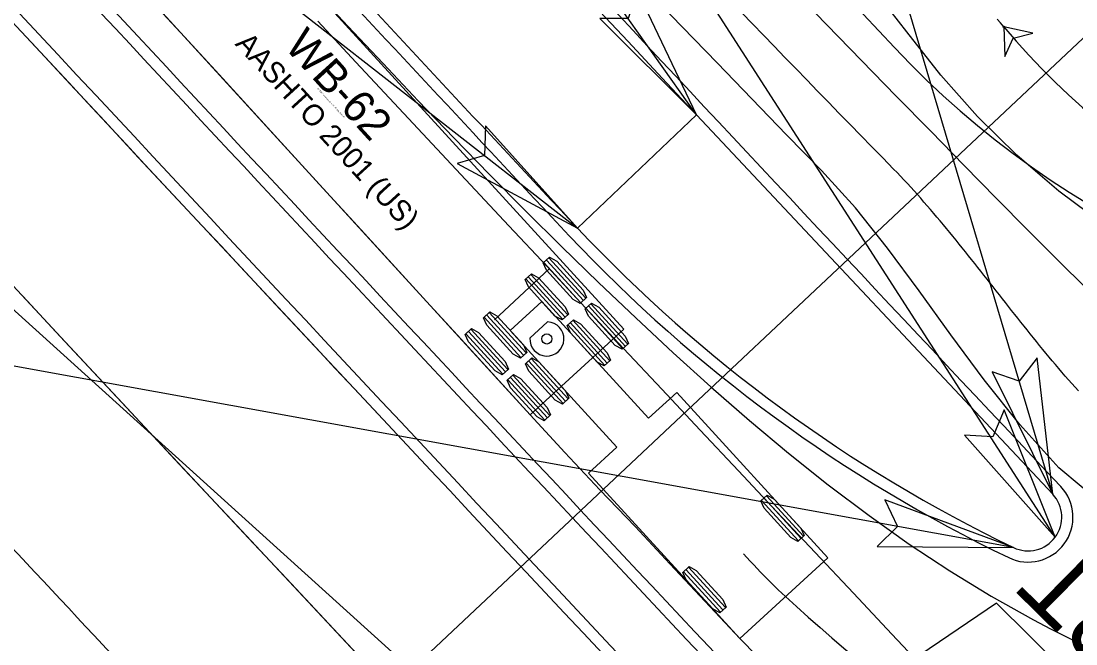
# Model space of a CAD drawing. Extents: x 1262642 to 1268358, y 767825 to 773481.
# Drawn here: x 1266689.1 to 1266759.8, y 772205.7 to 772247.4 of the extents above; entities that cross this region are included whole.
import ezdxf

# ---------------------------------------------------------------- set-up
doc = ezdxf.new("R2010")
doc.units = 0
for name, color, linetype in [('Prop Conc 1ft 6in Curb and Gutter', 7, 'Continuous'), ('Prop Conc 5in Monolithic Keyed In Island', 7, 'Continuous'), ('Prop Dimension Text', 7, 'Continuous'), ('Prop EOT', 7, 'Continuous'), ('Prop Horizontal Alignment', 7, 'Continuous'), ('Prop Horizontal Alignment Station Label', 7, 'Continuous'), ('Prop Horizontal Alignment Tick Small', 7, 'Continuous'), ('Prop Lane Lines', 7, 'Continuous'), ('Prop Paved Shoulder', 7, 'Continuous'), ('Prop Shade Light', 7, 'Continuous'), ('Prop Shade Medium', 7, 'Continuous'), ('Prop Terminator CELL', 7, 'Continuous'), ('Scratch_Level_3', 7, 'Continuous')]:
    doc.layers.add(name, color=color, linetype=linetype)

msp = doc.modelspace()

# ---------------------------------------------------------------- linework, layer by layer
at = {"layer": 'Prop Conc 1ft 6in Curb and Gutter'}
msp.add_line((1266726.388, 772233.528), (1266734.359, 772241.11), dxfattribs=at)
for radius, start, end in [(11385.75, 220.9464115, 223.1036607), (11396.75, 222.8296601, 223.1041091)]:
    msp.add_arc((1275047.307, 780021.225), radius, start, end, dxfattribs=at)
at = {"layer": 'Prop Conc 5in Monolithic Keyed In Island'}
msp.add_line((1266734.359, 772241.11), (1266758.201, 772215.712), dxfattribs=at)
for centre, radius, start, end in [((1275047.307, 780021.225), 11410.25, 222.8296601, 223.2792706), ((1275047.307, 780021.225), 11414.25, 222.8297896, 223.4298287), ((1266798.645, 772301.569), 99.25, 223.2788, 244.28592), ((1266756.558, 772214.175), 2.25, 244.28592, 43.10421)]:
    msp.add_arc(centre, radius, start, end, dxfattribs=at)
at = {"layer": 'Prop Dimension Text'}
for p, q in [((1266734.359, 772241.11), (1266654.367, 772353.573)), ((1266758.201, 772215.712), (1266729.837, 772311.282)), ((1266637.674, 772302.797), (1266726.388, 772233.528)), ((1266758.372, 772212.843), (1266700.467, 772302.683)), ((1266755.582, 772212.148), (1266643.887, 772232.407)), ((1266754.434, 772208.43), (1266782.15, 772181.121))]:
    msp.add_line(p, q, dxfattribs=at)
msp.add_lwpolyline([(1266754.434, 772208.43), (1266740.368, 772198.877)], dxfattribs=at)
at = {"layer": 'Prop EOT'}
for centre, radius, start, end in [((1275047.307, 780021.225), 11385, 222.8296601, 223.2789723), ((1275047.307, 780021.225), 11397.5, 222.8287756, 223.1041206), ((1275047.307, 780021.225), 11409.5, 222.8296601, 223.2792706), ((1275047.307, 780021.225), 11415, 222.8297896, 223.4298287), ((1266798.645, 772301.569), 100, 223.2788, 244.28592), ((1266840.27, 772443.458), 318.091, 223.23333, 243.65317), ((1275047.307, 780021.225), 11439, 222.9935866, 223.2588472), ((1266756.558, 772214.175), 3, 244.28592, 43.10421)]:
    msp.add_arc(centre, radius, start, end, dxfattribs=at)
at = {"layer": 'Prop Horizontal Alignment'}
msp.add_arc((1275047.307, 780021.225), 11400, 222.9935866, 225.4043192, dxfattribs=at)
at = {"layer": 'Prop Horizontal Alignment Station Label'}
for p, q in [((1266683.114, 772173.743), (1266860.999, 772340.982)), ((1266769.823, 772154.715), (1266566.881, 772338.064))]:
    msp.add_line(p, q, dxfattribs=at)
at = {"layer": 'Prop Horizontal Alignment Tick Small'}
msp.add_line((1266724.486, 772230.805), (1266720.835, 772227.388), dxfattribs=at)
at = {"layer": 'Prop Lane Lines'}
for centre, radius, start, end in [((1275047.307, 780021.225), 11373, 216.3649439, 223.1327476), ((1275047.307, 780021.225), 11427, 216.3674993, 223.5476842), ((1275047.307, 780021.225), 11415, 220.9464115, 223.1041206), ((1266791.4, 772286.629), 60, 223.13275, 315.73419), ((1275047.307, 780021.225), 11427, 222.9935866, 225.3637298)]:
    msp.add_arc(centre, radius, start, end, dxfattribs=at)
at = {"layer": 'Prop Paved Shoulder'}
for centre, radius, start, end in [((1275047.307, 780021.225), 11449, 220.5050908, 223.2024475), ((1266840.27, 772443.458), 314.091, 223.23333, 241.33253)]:
    msp.add_arc(centre, radius, start, end, dxfattribs=at)
at = {"layer": 'Prop Shade Light'}
for centre, radius, start, end in [((1275047.307, 780021.225), 11449, 220.5050908, 223.2024475), ((1266840.27, 772443.458), 314.091, 223.23333, 241.33253), ((1266840.27, 772443.458), 318.091, 223.23333, 243.65317), ((1275047.307, 780021.225), 11439, 222.9935866, 223.2588472)]:
    msp.add_arc(centre, radius, start, end, dxfattribs=at)
at = {"layer": 'Prop Shade Medium'}
for p, q in [((1266726.388, 772233.528), (1266734.359, 772241.11)), ((1266734.359, 772241.11), (1266758.201, 772215.712))]:
    msp.add_line(p, q, dxfattribs=at)
for centre, radius, start, end in [((1275047.307, 780021.225), 11410.25, 222.8296601, 223.2792706), ((1275047.307, 780021.225), 11414.25, 222.8297896, 223.4298287), ((1266798.645, 772301.569), 99.25, 223.2788, 244.28592), ((1266756.558, 772214.175), 2.25, 244.28592, 43.10421)]:
    msp.add_arc(centre, radius, start, end, dxfattribs=at)
at = {"layer": 'Prop Terminator CELL'}
for points in [[(1266727.879, 772247.545), (1266734.359, 772241.11), (1266730.417, 772249.412), (1266729.78, 772247.547)], [(1266718.341, 772237.845), (1266726.388, 772233.528), (1266720.24, 772240.359), (1266720.162, 772238.39)], [(1266754.152, 772223.898), (1266758.201, 772215.712), (1266757.158, 772224.843), (1266755.952, 772223.285)], [(1266752.301, 772219.665), (1266758.372, 772212.843), (1266754.949, 772221.372), (1266754.198, 772219.55)], [(1266746.45, 772212.229), (1266755.582, 772212.148), (1266746.963, 772215.337), (1266747.809, 772213.557)]]:
    msp.add_lwpolyline(points, close=True, dxfattribs=at)
at = {"layer": 'Scratch_Level_3'}
for p, q in [((1266729.506, 772226.762), (1266697.109, 772262.181)), ((1266690.837, 772256.444), (1266723.234, 772221.025)), ((1266726.621, 772228.528), (1266724.146, 772231.233)), ((1266726.79, 772228.682), (1266724.315, 772231.388)), ((1266726.959, 772228.837), (1266724.484, 772231.543)), ((1266725.572, 772227.569), (1266723.097, 772230.274)), ((1266725.741, 772227.723), (1266723.266, 772230.429)), ((1266725.403, 772227.414), (1266722.928, 772230.12)), ((1266723.997, 772228.612), (1266721.881, 772226.677)), ((1266731.14, 772220.803), (1266723.997, 772228.612)), ((1266729.433, 772225.453), (1266726.958, 772228.159)), ((1266729.602, 772225.608), (1266727.127, 772228.313)), ((1266729.771, 772225.763), (1266727.296, 772228.468)), ((1266722.611, 772224.861), (1266720.137, 772227.566)), ((1266722.78, 772225.015), (1266720.306, 772227.721)), ((1266722.95, 772225.17), (1266720.475, 772227.876)), ((1266721.732, 772224.056), (1266719.257, 772226.762)), ((1266724.396, 772227.249), (1266723.203, 772226.158)), ((1266723.234, 772221.025), (1266729.506, 772226.762)), ((1266728.215, 772224.34), (1266725.74, 772227.045)), ((1266728.384, 772224.494), (1266725.91, 772227.2)), ((1266728.553, 772224.649), (1266726.079, 772227.355)), ((1266729.506, 772226.762), (1266729.506, 772226.762)), ((1266721.394, 772223.747), (1266718.919, 772226.453)), ((1266721.563, 772223.902), (1266719.088, 772226.607)), ((1266721.881, 772226.677), (1266729.024, 772218.868)), ((1266725.593, 772221.941), (1266723.118, 772224.646)), ((1266725.762, 772222.095), (1266723.287, 772224.801)), ((1266725.424, 772221.786), (1266722.949, 772224.492)), ((1266724.206, 772220.672), (1266721.731, 772223.378)), ((1266724.375, 772220.827), (1266721.9, 772223.533)), ((1266724.544, 772220.982), (1266722.07, 772223.687)), ((1266733.033, 772222.535), (1266731.14, 772220.803)), ((1266743.157, 772211.467), (1266733.033, 772222.535)), ((1266729.024, 772218.868), (1266727.13, 772217.136)), ((1266727.13, 772217.136), (1266737.254, 772206.068)), ((1266741.357, 772212.757), (1266738.882, 772215.462)), ((1266741.526, 772212.911), (1266739.051, 772215.617)), ((1266741.188, 772212.602), (1266738.713, 772215.307)), ((1266737.254, 772206.068), (1266743.157, 772211.467)), ((1266743.157, 772211.467), (1266743.157, 772211.467)), ((1266735.961, 772207.821), (1266733.486, 772210.527)), ((1266736.13, 772207.976), (1266733.656, 772210.681)), ((1266736.299, 772208.13), (1266733.825, 772210.836))]:
    msp.add_line(p, q, dxfattribs=at)
for points in [[(1266760.466, 772229.481), (1266758.549, 772231.381), (1266756.544, 772233.398), (1266754.451, 772235.514), (1266752.278, 772237.719), (1266750.036, 772240.002), (1266747.735, 772242.353), (1266745.412, 772244.736), (1266743.093, 772247.124), (1266740.778, 772249.516), (1266738.467, 772251.912), (1266736.16, 772254.312), (1266733.857, 772256.716), (1266731.558, 772259.125), (1266729.263, 772261.537), (1266728.117, 772262.745)], [(1266761.603, 772214.984), (1266758.62, 772217.483), (1266755.997, 772220.375), (1266753.614, 772223.372), (1266751.395, 772226.376), (1266749.266, 772229.328), (1266747.155, 772232.178), (1266744.994, 772234.878), (1266742.725, 772237.376), (1266740.393, 772239.772), (1266738.065, 772242.171), (1266735.742, 772244.574), (1266733.422, 772246.981), (1266731.107, 772249.391), (1266728.796, 772251.805), (1266726.489, 772254.222), (1266724.185, 772256.644), (1266723.035, 772257.856)], [(1266690.837, 772256.444), (1266693.151, 772253.913), (1266695.463, 772251.382), (1266697.776, 772248.851), (1266700.092, 772246.323), (1266702.407, 772243.794), (1266704.721, 772241.264), (1266707.035, 772238.735), (1266709.349, 772236.205), (1266711.664, 772233.675), (1266713.978, 772231.145), (1266716.292, 772228.615), (1266718.606, 772226.085), (1266720.92, 772223.555), (1266723.234, 772221.025), (1266723.234, 772221.025), (1266725.546, 772218.51), (1266727.888, 772216.021), (1266730.244, 772213.547), (1266732.581, 772211.054), (1266734.918, 772208.561), (1266737.254, 772206.068), (1266737.254, 772206.068), (1266739.603, 772203.675)], [(1266708.695, 772249.546), (1266711.029, 772247.034), (1266713.374, 772244.533), (1266715.733, 772242.045), (1266718.109, 772239.573), (1266720.502, 772237.118), (1266722.916, 772234.683), (1266725.35, 772232.269), (1266727.807, 772229.878), (1266730.289, 772227.512), (1266732.789, 772225.184), (1266735.323, 772222.892), (1266737.896, 772220.646), (1266740.514, 772218.457), (1266743.183, 772216.334), (1266745.907, 772214.287), (1266745.907, 772214.287), (1266748.603, 772212.383), (1266751.319, 772210.594), (1266754.085, 772208.902), (1266756.909, 772207.314), (1266758.054, 772206.709)], [(1266796.344, 772224.878), (1266792.813, 772224.356), (1266789.186, 772224.25), (1266785.516, 772224.574), (1266781.868, 772225.177), (1266778.27, 772226.026), (1266774.738, 772227.117), (1266771.287, 772228.446), (1266767.935, 772230.007), (1266764.697, 772231.792), (1266761.587, 772233.794), (1266758.621, 772236.002), (1266755.811, 772238.406), (1266753.171, 772240.996), (1266750.714, 772243.76), (1266748.433, 772246.659), (1266746.21, 772249.534)], [(1266754.921, 772246.999), (1266754.707, 772247.254), (1266754.494, 772247.51)], [(1266759.924, 772222.627), (1266759.702, 772222.875), (1266759.481, 772223.125), (1266759.261, 772223.375), (1266759.042, 772223.627), (1266758.824, 772223.879), (1266758.608, 772224.133), (1266758.392, 772224.387), (1266758.178, 772224.642), (1266757.964, 772224.898), (1266757.751, 772225.154), (1266757.539, 772225.412), (1266757.328, 772225.67), (1266757.118, 772225.928), (1266756.908, 772226.187), (1266756.699, 772226.447), (1266756.49, 772226.707), (1266756.282, 772226.967), (1266756.075, 772227.228), (1266755.868, 772227.489), (1266755.661, 772227.751), (1266755.455, 772228.013), (1266755.249, 772228.275), (1266755.043, 772228.537), (1266754.837, 772228.799), (1266754.631, 772229.061), (1266754.426, 772229.324), (1266754.22, 772229.586), (1266754.014, 772229.848), (1266753.808, 772230.11), (1266753.602, 772230.373), (1266753.396, 772230.634), (1266753.19, 772230.896), (1266752.983, 772231.158), (1266752.776, 772231.419), (1266752.568, 772231.68), (1266752.36, 772231.94), (1266752.152, 772232.2), (1266751.943, 772232.46), (1266751.733, 772232.719), (1266751.522, 772232.977), (1266751.311, 772233.235), (1266751.099, 772233.492), (1266750.886, 772233.748), (1266750.672, 772234.004), (1266750.457, 772234.259), (1266750.241, 772234.513), (1266750.024, 772234.766), (1266749.806, 772235.018), (1266749.587, 772235.269), (1266749.367, 772235.52), (1266749.145, 772235.769), (1266748.922, 772236.016), (1266748.698, 772236.263), (1266748.473, 772236.508), (1266748.245, 772236.752), (1266748.017, 772236.995), (1266747.787, 772237.236), (1266747.555, 772237.476)], [(1266737.506, 772211.719), (1266737.731, 772211.473), (1266737.958, 772211.228), (1266738.186, 772210.985), (1266738.415, 772210.744), (1266738.647, 772210.504), (1266738.88, 772210.265), (1266739.114, 772210.028), (1266739.35, 772209.793), (1266739.588, 772209.56), (1266739.828, 772209.328), (1266740.069, 772209.098), (1266740.312, 772208.869), (1266740.556, 772208.643), (1266740.802, 772208.418), (1266741.05, 772208.195)], [(1266758.054, 772206.709), (1266759.789, 772205.836), (1266762.724, 772204.476), (1266765.71, 772203.241), (1266768.74, 772202.14), (1266771.799, 772201.18), (1266774.867, 772200.369), (1266777.932, 772199.711), (1266780.996, 772199.204), (1266783.988, 772198.853), (1266786.887, 772198.651), (1266789.688, 772198.586), (1266792.42, 772198.647), (1266795.121, 772198.831), (1266797.787, 772199.135), (1266800.414, 772199.559), (1266803.004, 772200.1), (1266805.549, 772200.756), (1266808.059, 772201.531), (1266810.499, 772202.411), (1266812.883, 772203.399), (1266815.228, 772204.498), (1266815.459, 772204.613)]]:
    msp.add_lwpolyline(points, dxfattribs=at)
for points in [[(1266754.921, 772246.999), (1266755.006, 772245), (1266755.563, 772246.232), (1266756.873, 772246.563)], [(1266727.001, 772228.875), (1266726.579, 772228.489), (1266726.105, 772228.752), (1266724.323, 772230.7), (1266724.104, 772231.195), (1266724.526, 772231.581), (1266725, 772231.319), (1266726.781, 772229.371)], [(1266725.783, 772227.762), (1266725.361, 772227.376), (1266724.887, 772227.638), (1266723.106, 772229.586), (1266722.886, 772230.081), (1266723.308, 772230.467), (1266723.782, 772230.205), (1266725.564, 772228.257)], [(1266729.813, 772225.801), (1266729.391, 772225.415), (1266728.917, 772225.677), (1266727.135, 772227.625), (1266726.916, 772228.12), (1266727.338, 772228.507), (1266727.812, 772228.244), (1266729.594, 772226.296)], [(1266722.992, 772225.208), (1266722.569, 772224.822), (1266722.096, 772225.085), (1266720.314, 772227.033), (1266720.095, 772227.528), (1266720.517, 772227.914), (1266720.99, 772227.651), (1266722.772, 772225.703)], [(1266721.774, 772224.095), (1266721.352, 772223.709), (1266720.878, 772223.971), (1266719.096, 772225.919), (1266718.877, 772226.414), (1266719.299, 772226.8), (1266719.773, 772226.538), (1266721.555, 772224.59)], [(1266728.595, 772224.687), (1266728.173, 772224.301), (1266727.7, 772224.564), (1266725.918, 772226.512), (1266725.699, 772227.007), (1266726.121, 772227.393), (1266726.594, 772227.13), (1266728.376, 772225.182)], [(1266725.804, 772222.134), (1266725.382, 772221.748), (1266724.908, 772222.01), (1266723.126, 772223.958), (1266722.907, 772224.453), (1266723.329, 772224.839), (1266723.803, 772224.577), (1266725.584, 772222.629)], [(1266724.586, 772221.02), (1266724.164, 772220.634), (1266723.691, 772220.897), (1266721.909, 772222.845), (1266721.689, 772223.34), (1266722.111, 772223.726), (1266722.585, 772223.463), (1266724.367, 772221.515)], [(1266741.568, 772212.95), (1266741.146, 772212.564), (1266740.672, 772212.826), (1266738.89, 772214.774), (1266738.671, 772215.269), (1266739.093, 772215.655), (1266739.567, 772215.393), (1266741.349, 772213.445)], [(1266736.341, 772208.169), (1266735.919, 772207.783), (1266735.446, 772208.045), (1266733.664, 772209.993), (1266733.444, 772210.488), (1266733.867, 772210.874), (1266734.34, 772210.612), (1266736.122, 772208.664)]]:
    msp.add_lwpolyline(points, close=True, dxfattribs=at)
for centre, radius in [((1266754.921, 772246.999), 0.0417), ((1266754.921, 772246.999), 0.0417), ((1266724.345, 772226.108), 0.34)]:
    msp.add_circle(centre, radius, dxfattribs=at)
for centre, radius, start, end in [((1268163.048, 773623.07), 1980.781, 222.458728, 224.388454), ((1266792.555, 772278.491), 49.072, 219.92261, 266.69799), ((1266724.345, 772226.108), 1.143, 177.44899, 87.44899), ((1266882.309, 772367.05), 212.577, 228.35539, 237.4405)]:
    msp.add_arc(centre, radius, start, end, dxfattribs=at)

# ---------------------------------------------------------------- texts
at = {"layer": 'Prop Dimension Text'}
msp.add_text("10.25' RT", height=5, rotation=135.42387, dxfattribs=at).set_placement((1266779.672, 772192.586))
at = {"layer": 'Scratch_Level_3'}
for s, height, p in [('WB-62', 2.125, (1266706.711, 772245.638)), ('AASHTO 2001 (US)', 1.41667, (1266703.425, 772245.82)), ('(c) 2016 Transoft Solutions, Inc. All rights reserved.', 0.085, (1266708.971, 772242.853))]:
    msp.add_text(s, height=height, rotation=312.44899, dxfattribs=at).set_placement(p)

doc.saveas('drawing.dxf')
